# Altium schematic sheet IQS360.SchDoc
size A3; CheckedBy: XXX; Author: DO NOT USE THIS PARAMETER; CompanyName: Azoteq (Pty) Ltd; Engineer: DO NOT USE THIS PARAMETER; SheetNumber: 1; SheetTotal: 2; Sheet_Title: Sheet x
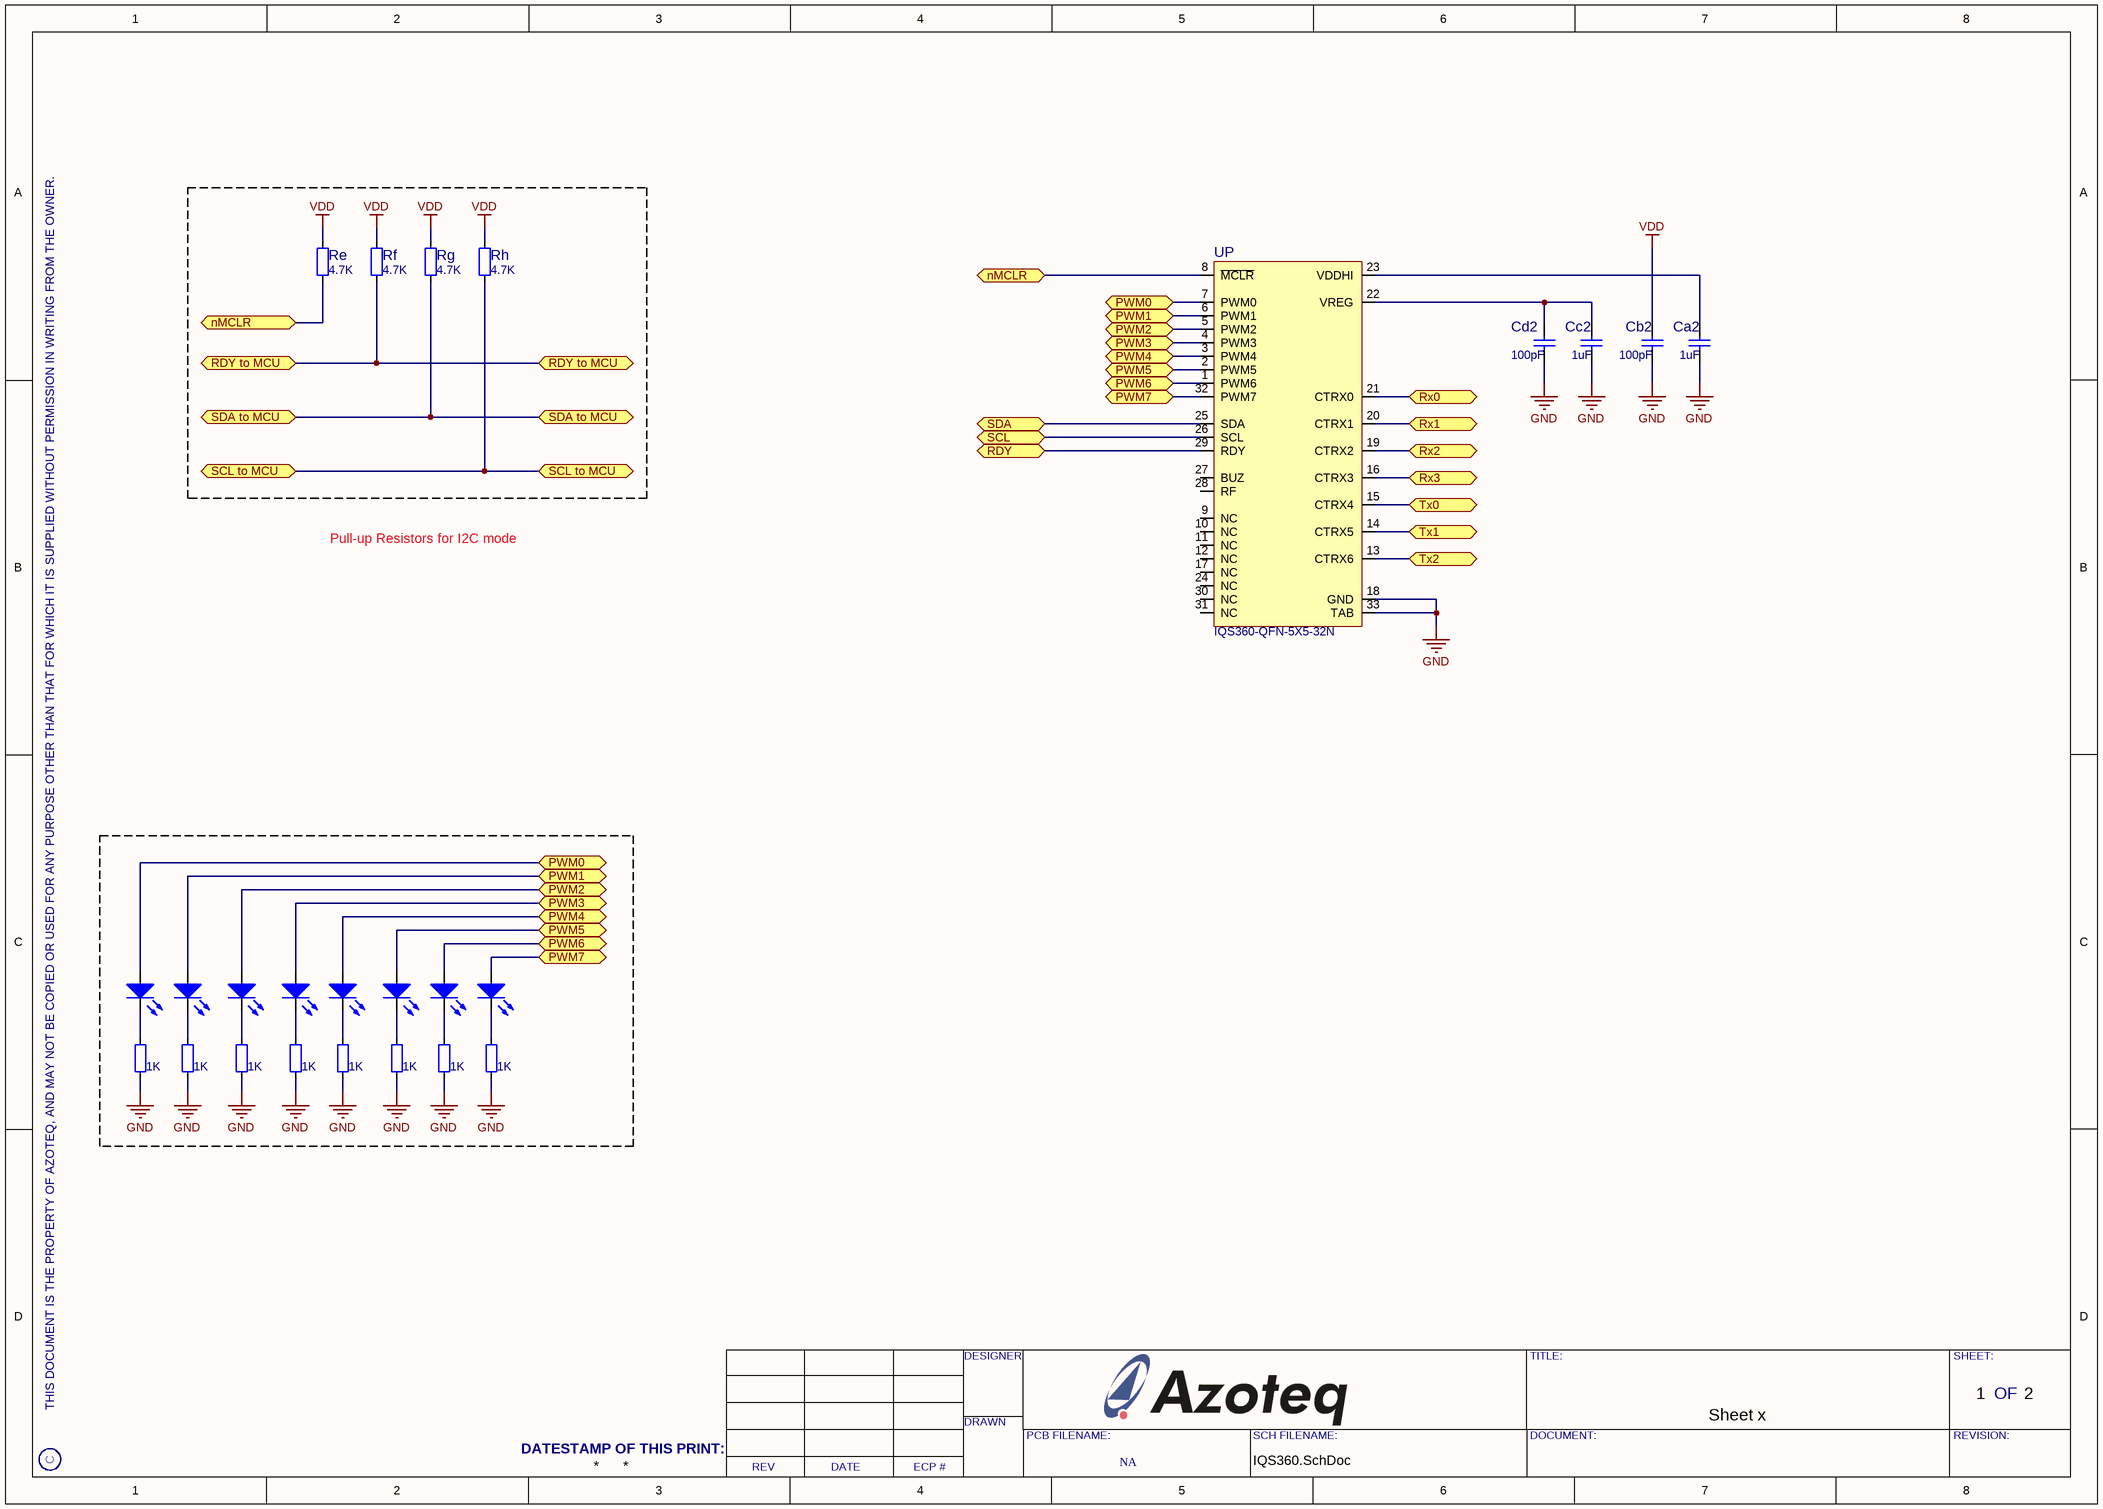
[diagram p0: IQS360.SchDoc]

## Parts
Ca2  1uF  [C-0402]
Cb2  100pF  [C-0402]
Cc2  1uF  [C-0402]
Cd2  100pF  [C-0402]
DS1  KPT-1608ID  [D-LED-RED-0603]  (value not drawn)
DS2  KPT-1608ID  [D-LED-RED-0603]  (value not drawn)
DS3  KPT-1608ID  [D-LED-RED-0603]  (value not drawn)
DS4  KPT-1608ID  [D-LED-RED-0603]  (value not drawn)
DS5  KPT-1608ID  [D-LED-RED-0603]  (value not drawn)
DS6  KPT-1608ID  [D-LED-RED-0603]  (value not drawn)
DS7  KPT-1608ID  [D-LED-RED-0603]  (value not drawn)
DS8  KPT-1608ID  [D-LED-RED-0603]  (value not drawn)
R1  1K  [R-0603]
R2  1K  [R-0603]
R3  1K  [R-0603]
R4  1K  [R-0603]
R5  1K  [R-0603]
R6  1K  [R-0603]
R7  1K  [R-0603]
R8  1K  [R-0603]
Re  4.7K  [R-0603]
Rf  4.7K  [R-0603]
Rg  4.7K  [R-0603]
Rh  4.7K  [R-0603]
UP  IQS360-QFN-5X5-32N  [U-QFN-P0.5-5x5-32]

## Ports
nMCLR, PWM0, PWM1, PWM2, PWM3, PWM4, PWM5, PWM6, PWM7, RDY, RDY to MCU, Rx0, Rx1, Rx2, Rx3, SCL, SCL to MCU, SDA , SDA to MCU, Tx0, Tx1, Tx2

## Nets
GND: Ca2.2 Cb2.2 Cc2.2 Cd2.2 R1.1 R2.1 R3.1 R4.1 R5.1 R6.1 R7.1 R8.1 UP.18(GND) UP.33(TAB)
VDD: Cb2.1 Re.1 Rf.1 Rg.1 Rh.1
nMCLR: Re.2 UP.8(~{MCLR}) ; port nMCLR
PWM0: DS1.2(A) UP.7(PWM0) ; port PWM0
PWM1: DS2.2(A) UP.6(PWM1) ; port PWM1
PWM2: DS3.2(A) UP.5(PWM2) ; port PWM2
PWM3: DS4.2(A) UP.4(PWM3) ; port PWM3
PWM4: DS5.2(A) UP.3(PWM4) ; port PWM4
PWM5: DS6.2(A) UP.2(PWM5) ; port PWM5
PWM6: DS7.2(A) UP.1(PWM6) ; port PWM6
PWM7: DS8.2(A) UP.32(PWM7) ; port PWM7
RDY: UP.29(RDY) ; port RDY
RDY to MCU: Rf.2 ; port RDY to MCU
Rx0: UP.21(CTRX0) ; port Rx0
Rx1: UP.20(CTRX1) ; port Rx1
Rx2: UP.19(CTRX2) ; port Rx2
Rx3: UP.16(CTRX3) ; port Rx3
SCL: UP.26(SCL) ; port SCL
SCL to MCU: Rh.2 ; port SCL to MCU
SDA : UP.25(SDA) ; port SDA 
SDA to MCU: Rg.2 ; port SDA to MCU
Tx0: UP.15(CTRX4) ; port Tx0
Tx1: UP.14(CTRX5) ; port Tx1
Tx2: UP.13(CTRX6) ; port Tx2
NetCa2_1: Ca2.1 UP.23(VDDHI)
NetCc2_1: Cc2.1 Cd2.1 UP.22(VREG)
NetDS1_1: DS1.1(K) R1.2
NetDS2_1: DS2.1(K) R2.2
NetDS3_1: DS3.1(K) R3.2
NetDS4_1: DS4.1(K) R4.2
NetDS5_1: DS5.1(K) R5.2
NetDS6_1: DS6.1(K) R6.2
NetDS7_1: DS7.1(K) R7.2
NetDS8_1: DS8.1(K) R8.2

Not connected (* = marked no-connect by the designer): UP 9(NC) 10(NC) 11(NC) 12(NC) 17(NC) 24(NC) 27(BUZ) 28(RF) 30(NC) 31(NC)

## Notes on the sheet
- Pull-up Resistors for I2C mode
- NA

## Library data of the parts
Ca2 Cb2 Cc2 Cd2 = CAP 12pF 0402 CER NPO 5% 50V: Capacitor, Ceramic, 12pF, 0402, NPO, 5%, 50V; Generated_By: GHM; Pin_Count: 2
DS1-DS8 = LED-KPT1608ID-RED-0603: Manufacturer: KingBright; Generated_By: GHM
R1-R8 = RES 4K7 0603 1% 0.1W: Int_Part_Number: RES0003; Tolerance: 1%; Wattage: 0.1W; Generated_By: GHM; Value: 4.7K
Re Rf Rg Rh = RES 4K7 0603 1% 0.1W: Int_Part_Number: RES0003; Tolerance: 1%; Wattage: 0.1W; Generated_By: GHM
UP = IQS333-QFN-5X5-32N: IQS333, QFN-5X5-32N, Azoteq IQS333; Manufacturer_PN: IQS360; Generated_By: GHM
